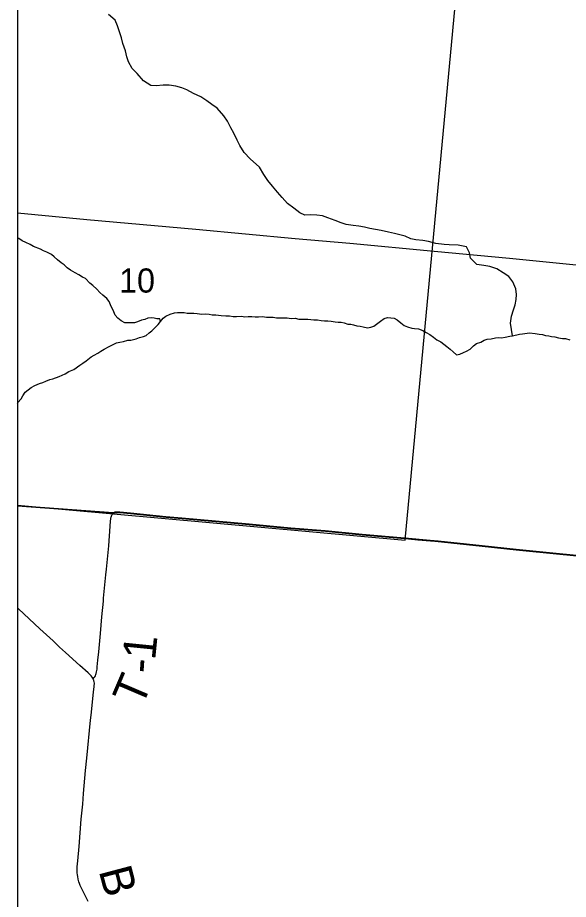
# Model space of a CAD drawing. Extents: x 0 to 34, y 0 to 22.
# Drawn here: x 22.516 to 23.47, y 18.35 to 19.877 of the extents above; entities that cross this region are included whole.
import ezdxf

# ---------------------------------------------------------------- set-up
doc = ezdxf.new("R2010")
doc.units = 0
for name, color, linetype in [('GM_X_County_Road', 7, 'Continuous'), ('GM_X_Minor_River', 7, 'Continuous'), ('GM_X_Section_Text', 7, 'Continuous'), ('GM_X_Township_Road', 7, 'Continuous'), ('GM_X_Township_Road_Text', 7, 'Continuous'), ('SH_Border', 7, 'Continuous'), ('SH_Data', 7, 'Continuous')]:
    doc.layers.add(name, color=color, linetype=linetype)

msp = doc.modelspace()

# ---------------------------------------------------------------- linework, layer by layer
at = {"layer": 'GM_X_County_Road'}
msp.add_lwpolyline([(22.5164, 20.0408), (22.5164, 19.0327), (23.1878, 18.972), (23.2813, 19.9719)], close=True, dxfattribs=at)
msp.add_lwpolyline([(22.5164, 19.5392), (22.6361, 19.5278), (22.825, 19.5105), (22.9974, 19.4949), (23.092, 19.4868), (23.2382, 19.4727), (23.3684, 19.4604), (23.5242, 19.4452), (23.6564, 19.4321), (23.6852, 19.4293)], dxfattribs=at)
at = {"layer": 'GM_X_Minor_River'}
for points in [[(23.3737, 19.3259), (23.37, 19.3479), (23.3721, 19.36), (23.3754, 19.371), (23.3782, 19.3797), (23.3799, 19.3892), (23.3805, 19.3979), (23.3795, 19.4074), (23.3741, 19.4197), (23.3671, 19.4286), (23.3573, 19.4349), (23.3468, 19.4419), (23.3344, 19.4463), (23.3238, 19.4481), (23.3117, 19.4495), (23.3009, 19.4603), (23.2992, 19.4699), (23.2941, 19.4802), (23.2798, 19.4828), (23.2642, 19.4839), (23.2551, 19.4841), (23.2411, 19.4859), (23.2283, 19.4892), (23.2181, 19.4909), (23.2063, 19.4923), (23.1977, 19.494), (23.1879, 19.4984), (23.1784, 19.5012), (23.169, 19.5033), (23.1588, 19.5054), (23.1463, 19.5083), (23.1361, 19.5104), (23.1263, 19.5122), (23.1172, 19.5142), (23.1074, 19.516), (23.0979, 19.5169), (23.0855, 19.5191), (23.0768, 19.5219), (23.0666, 19.5259), (23.0535, 19.5304), (23.0444, 19.5336), (23.035, 19.5353), (23.0243, 19.5355), (23.0141, 19.5353), (23.0051, 19.5393), (22.995, 19.5471), (22.9838, 19.555), (22.9745, 19.5654), (22.9667, 19.5747), (22.9582, 19.5855), (22.9501, 19.5952), (22.9431, 19.6056), (22.9354, 19.6183), (22.9193, 19.6327), (22.9089, 19.6435), (22.9016, 19.6558), (22.8968, 19.6651), (22.891, 19.677), (22.8859, 19.6862), (22.8797, 19.6977), (22.8734, 19.707), (22.8619, 19.7205), (22.853, 19.7264), (22.8444, 19.733), (22.8335, 19.7397), (22.8211, 19.746), (22.8095, 19.7523), (22.8008, 19.7556), (22.7902, 19.7584), (22.7789, 19.7602), (22.7683, 19.7604), (22.7565, 19.7591), (22.747, 19.7593), (22.7347, 19.7675), (22.7235, 19.7803), (22.715, 19.7888), (22.7084, 19.8008), (22.7055, 19.8095), (22.7031, 19.8195), (22.6988, 19.8325), (22.6964, 19.8424), (22.6931, 19.8524), (22.6896, 19.8627), (22.6852, 19.8727), (22.6737, 19.8828)], [(22.7638, 19.3511), (22.7627, 19.3553), (22.7577, 19.3557), (22.7528, 19.3564), (22.7475, 19.3572), (22.7418, 19.3564), (22.7368, 19.3545), (22.7307, 19.353), (22.7243, 19.3503), (22.7186, 19.3484), (22.7091, 19.3488), (22.7022, 19.3488), (22.6957, 19.3522), (22.69, 19.3564), (22.6855, 19.3621), (22.6828, 19.3674), (22.6775, 19.3796), (22.6748, 19.3853), (22.671, 19.3906), (22.6642, 19.3967), (22.6585, 19.4009), (22.6535, 19.407), (22.6467, 19.413), (22.6414, 19.4172), (22.6341, 19.4256), (22.6288, 19.4275), (22.6224, 19.4316), (22.6159, 19.4351), (22.6079, 19.44), (22.6022, 19.4438), (22.5969, 19.4491), (22.5919, 19.4525), (22.5855, 19.4575), (22.5798, 19.4628), (22.5748, 19.467), (22.5672, 19.4708), (22.5611, 19.4731), (22.5558, 19.4761), (22.544, 19.481), (22.5379, 19.4845), (22.5307, 19.4879), (22.5243, 19.4905), (22.5182, 19.4947), (22.5164, 19.4957)], [(22.5164, 19.2096), (22.517, 19.2106), (22.5224, 19.217), (22.5254, 19.2223), (22.5296, 19.2284), (22.5345, 19.2326), (22.5399, 19.2364), (22.5459, 19.2402), (22.5543, 19.2436), (22.56, 19.2455), (22.5653, 19.2478), (22.5722, 19.2504), (22.5775, 19.2516), (22.5881, 19.2554), (22.5938, 19.2577), (22.5988, 19.2603), (22.6053, 19.2645), (22.6136, 19.2679), (22.6243, 19.2755), (22.6296, 19.2789), (22.6349, 19.2827), (22.6437, 19.2896), (22.649, 19.2926), (22.6551, 19.296), (22.6604, 19.2994), (22.6661, 19.3032), (22.6748, 19.3074), (22.6805, 19.3105), (22.6874, 19.3139), (22.6935, 19.315), (22.6999, 19.3165), (22.7075, 19.3188), (22.7125, 19.3188), (22.722, 19.3211), (22.7277, 19.323), (22.7342, 19.3249), (22.7391, 19.3264), (22.744, 19.331), (22.749, 19.3348), (22.7551, 19.3408), (22.7596, 19.3458), (22.7638, 19.3511), (22.7684, 19.3568), (22.7733, 19.3602), (22.7805, 19.3636), (22.7881, 19.3659), (22.7931, 19.3663), (22.7992, 19.3663), (22.8049, 19.3667), (22.8102, 19.3655), (22.8216, 19.3655), (22.8273, 19.3648), (22.8357, 19.3636), (22.8421, 19.364), (22.8482, 19.3636), (22.8535, 19.3625), (22.86, 19.3625), (22.8691, 19.361)], [(22.8691, 19.361), (22.8771, 19.3606), (22.8832, 19.3606), (22.89, 19.3598), (22.8958, 19.3598), (22.9045, 19.3602), (22.9102, 19.359), (22.9159, 19.3594), (22.922, 19.3594), (22.9281, 19.359), (22.9338, 19.359), (22.9406, 19.3594), (22.9478, 19.3583), (22.9589, 19.3583), (22.965, 19.3575), (22.9703, 19.3571), (22.9756, 19.3575), (22.9832, 19.3575), (22.99, 19.356), (22.9969, 19.3564), (23.0037, 19.3548), (23.0129, 19.3552), (23.0193, 19.3548), (23.0243, 19.3541), (23.0296, 19.3537), (23.0361, 19.3537), (23.0425, 19.3526), (23.0478, 19.3518), (23.0539, 19.3518), (23.0596, 19.3514), (23.0665, 19.3503), (23.0718, 19.3499), (23.0767, 19.3495), (23.0821, 19.3484), (23.0882, 19.3465), (23.0935, 19.3461), (23.0984, 19.3453), (23.1041, 19.3434), (23.1098, 19.3427), (23.1148, 19.3419), (23.1224, 19.34), (23.1285, 19.3411), (23.1334, 19.343), (23.1383, 19.3461), (23.1452, 19.3514), (23.1513, 19.3563), (23.157, 19.3578), (23.1627, 19.3575), (23.1688, 19.3567), (23.1741, 19.3537), (23.1802, 19.3483), (23.1859, 19.3442), (23.192, 19.3419), (23.1992, 19.3392), (23.2041, 19.3388), (23.211, 19.3381), (23.2182, 19.3354), (23.2243, 19.332), (23.2307, 19.3286), (23.2368, 19.324), (23.2429, 19.3194), (23.2494, 19.3156), (23.26, 19.3073), (23.2657, 19.3031), (23.2707, 19.2982), (23.2764, 19.2932), (23.2825, 19.2944), (23.2889, 19.2974), (23.2939, 19.2997), (23.3003, 19.3031), (23.306, 19.3088), (23.3114, 19.3126), (23.319, 19.3152), (23.3247, 19.3183), (23.33, 19.3202), (23.3368, 19.3209), (23.3441, 19.3228), (23.3494, 19.3232), (23.3547, 19.3228), (23.3612, 19.3236), (23.3688, 19.3255), (23.3737, 19.3259), (23.3859, 19.3289), (23.3912, 19.3297), (23.4034, 19.3312), (23.4129, 19.33), (23.4201, 19.3289), (23.4254, 19.3281), (23.4311, 19.3266), (23.4364, 19.3258), (23.4414, 19.3251), (23.4471, 19.3243), (23.4536, 19.3224), (23.4604, 19.3217), (23.4653, 19.3213), (23.473, 19.319)]]:
    msp.add_lwpolyline(points, dxfattribs=at)
at = {"layer": 'GM_X_Township_Road'}
for points in [[(22.6649, 18.8668), (22.6654, 18.8717), (22.6694, 18.9121), (22.6702, 18.9217), (22.6741, 18.9622), (22.6768, 18.9965), (22.6772, 19.0049), (22.6776, 19.0091), (22.6779, 19.0106), (22.6783, 19.0123), (22.6788, 19.0137), (22.6796, 19.0154), (22.6803, 19.0165), (22.6812, 19.0177), (22.6818, 19.0183), (22.6823, 19.0188)], [(22.6823, 19.0188), (22.6832, 19.0193), (22.6841, 19.0197), (22.6852, 19.02), (22.6865, 19.0203), (22.6879, 19.0203), (22.6894, 19.0202), (22.6936, 19.02), (22.7122, 19.0183), (22.7735, 19.0123), (22.8013, 19.0099), (22.9176, 18.9993), (22.9896, 18.9926), (23.0495, 18.9875), (23.1132, 18.9816), (23.1936, 18.9743), (23.2095, 18.973)], [(23.2095, 18.973), (23.2315, 18.9712), (23.2393, 18.9704)], [(23.2393, 18.9704), (23.2452, 18.9698), (23.2668, 18.9674), (23.3212, 18.962), (23.3803, 18.9554), (23.4555, 18.9481), (23.5092, 18.9429)], [(22.6472, 18.7321), (22.6492, 18.7344), (22.65, 18.7356), (22.651, 18.7374), (22.6519, 18.7393), (22.6526, 18.7415), (22.6531, 18.7439), (22.6539, 18.7489), (22.6542, 18.7526), (22.6548, 18.7588), (22.6553, 18.7644), (22.6568, 18.7786), (22.658, 18.7916), (22.6597, 18.8108), (22.6624, 18.8393), (22.6649, 18.8668)], [(22.6472, 18.7321), (22.6466, 18.7332), (22.6453, 18.7351), (22.6435, 18.7371), (22.6383, 18.7422), (22.6241, 18.7552), (22.5993, 18.7778), (22.5892, 18.787), (22.5778, 18.7976), (22.5551, 18.8187), (22.5176, 18.8531), (22.5164, 18.8541)], [(22.6383, 18.3463), (22.6264, 18.3706), (22.6247, 18.3743), (22.6235, 18.3775), (22.6226, 18.3803), (22.6214, 18.3852), (22.6204, 18.3895), (22.6199, 18.3926), (22.6195, 18.3959), (22.6194, 18.3996), (22.6194, 18.402), (22.6197, 18.4063), (22.6207, 18.4169), (22.6229, 18.4416), (22.6247, 18.4651), (22.6267, 18.4892), (22.6291, 18.5152), (22.6306, 18.5332), (22.6342, 18.5734), (22.6361, 18.5944), (22.6427, 18.6606), (22.6436, 18.6692), (22.6478, 18.7088), (22.6489, 18.7186), (22.6491, 18.7207), (22.6493, 18.7231), (22.6493, 18.7247), (22.6489, 18.7267), (22.6486, 18.728), (22.6482, 18.7295), (22.6478, 18.7305), (22.6472, 18.7321)]]:
    msp.add_lwpolyline(points, dxfattribs=at)
at = {"layer": 'SH_Border'}
for points in [[(22.5164, 20.2618), (22.5164, 19.0318), (22.6821, 19.0193), (22.683, 19.0198), (22.6839, 19.0202), (22.685, 19.0206), (22.6862, 19.0208), (22.6877, 19.0209), (22.6892, 19.0208), (22.6934, 19.0205), (22.712, 19.0188), (22.7733, 19.0128), (22.801, 19.0104), (22.9174, 18.9999), (22.9894, 18.9932), (23.0493, 18.9881), (23.113, 18.9821), (23.1934, 18.9749), (23.2312, 18.9717), (23.2449, 18.9704), (23.2666, 18.968), (23.3209, 18.9625), (23.3801, 18.9559), (23.4553, 18.9486), (23.509, 18.9435)], [(23.509, 18.9435), (23.4553, 18.9486), (23.3801, 18.9559), (23.3209, 18.9625), (23.2666, 18.968), (23.2449, 18.9704), (23.2312, 18.9717), (23.1934, 18.9749), (23.113, 18.9821), (23.0493, 18.9881), (22.9894, 18.9932), (22.9174, 18.9999), (22.801, 19.0104), (22.7733, 19.0128), (22.712, 19.0188), (22.6934, 19.0205), (22.6892, 19.0208), (22.6877, 19.0209), (22.6862, 19.0208), (22.685, 19.0206), (22.6839, 19.0202), (22.683, 19.0198), (22.6821, 19.0193), (22.5164, 19.0318), (22.5164, 14.9743)]]:
    msp.add_lwpolyline(points, dxfattribs=at)
at = {"layer": 'SH_Data'}
msp.add_line((22.5164, 20.2618), (22.5164, 13.4618), dxfattribs=at)
for points in [[(22.5164, 20.2618), (22.5164, 19.0318), (22.6821, 19.0193), (22.683, 19.0198), (22.6839, 19.0202), (22.685, 19.0206), (22.6862, 19.0208), (22.6877, 19.0209), (22.6892, 19.0208), (22.6934, 19.0205), (22.712, 19.0188), (22.7733, 19.0128), (22.801, 19.0104), (22.9174, 18.9999), (22.9894, 18.9932), (23.0493, 18.9881), (23.113, 18.9821), (23.1934, 18.9749), (23.2312, 18.9717), (23.2449, 18.9704), (23.2666, 18.968), (23.3209, 18.9625), (23.3801, 18.9559), (23.4553, 18.9486), (23.509, 18.9435)], [(23.509, 18.9435), (23.4553, 18.9486), (23.3801, 18.9559), (23.3209, 18.9625), (23.2666, 18.968), (23.2449, 18.9704), (23.2312, 18.9717), (23.1934, 18.9749), (23.113, 18.9821), (23.0493, 18.9881), (22.9894, 18.9932), (22.9174, 18.9999), (22.801, 19.0104), (22.7733, 19.0128), (22.712, 19.0188), (22.6934, 19.0205), (22.6892, 19.0208), (22.6877, 19.0209), (22.6862, 19.0208), (22.685, 19.0206), (22.6839, 19.0202), (22.683, 19.0198), (22.6821, 19.0193), (22.5164, 19.0318), (22.5164, 13.4618)]]:
    msp.add_lwpolyline(points, dxfattribs=at)

# ---------------------------------------------------------------- texts
at = {"layer": 'GM_X_Section_Text'}
msp.add_text('10', height=0.04186, rotation=0, dxfattribs=at).set_placement((22.6921, 19.4009))
at = {"layer": 'GM_X_Township_Road_Text'}
for s, rotation, p in [('1', 84.2739, (22.7545, 18.7634)), ('-', 86.2882, (22.7531, 18.7406)), ('T', 66.9291, (22.7316, 18.6813)), ('B', 284.8305, (22.6566, 18.3998))]:
    msp.add_text(s, height=0.0568, rotation=rotation, dxfattribs=at).set_placement(p)

doc.saveas('drawing.dxf')
